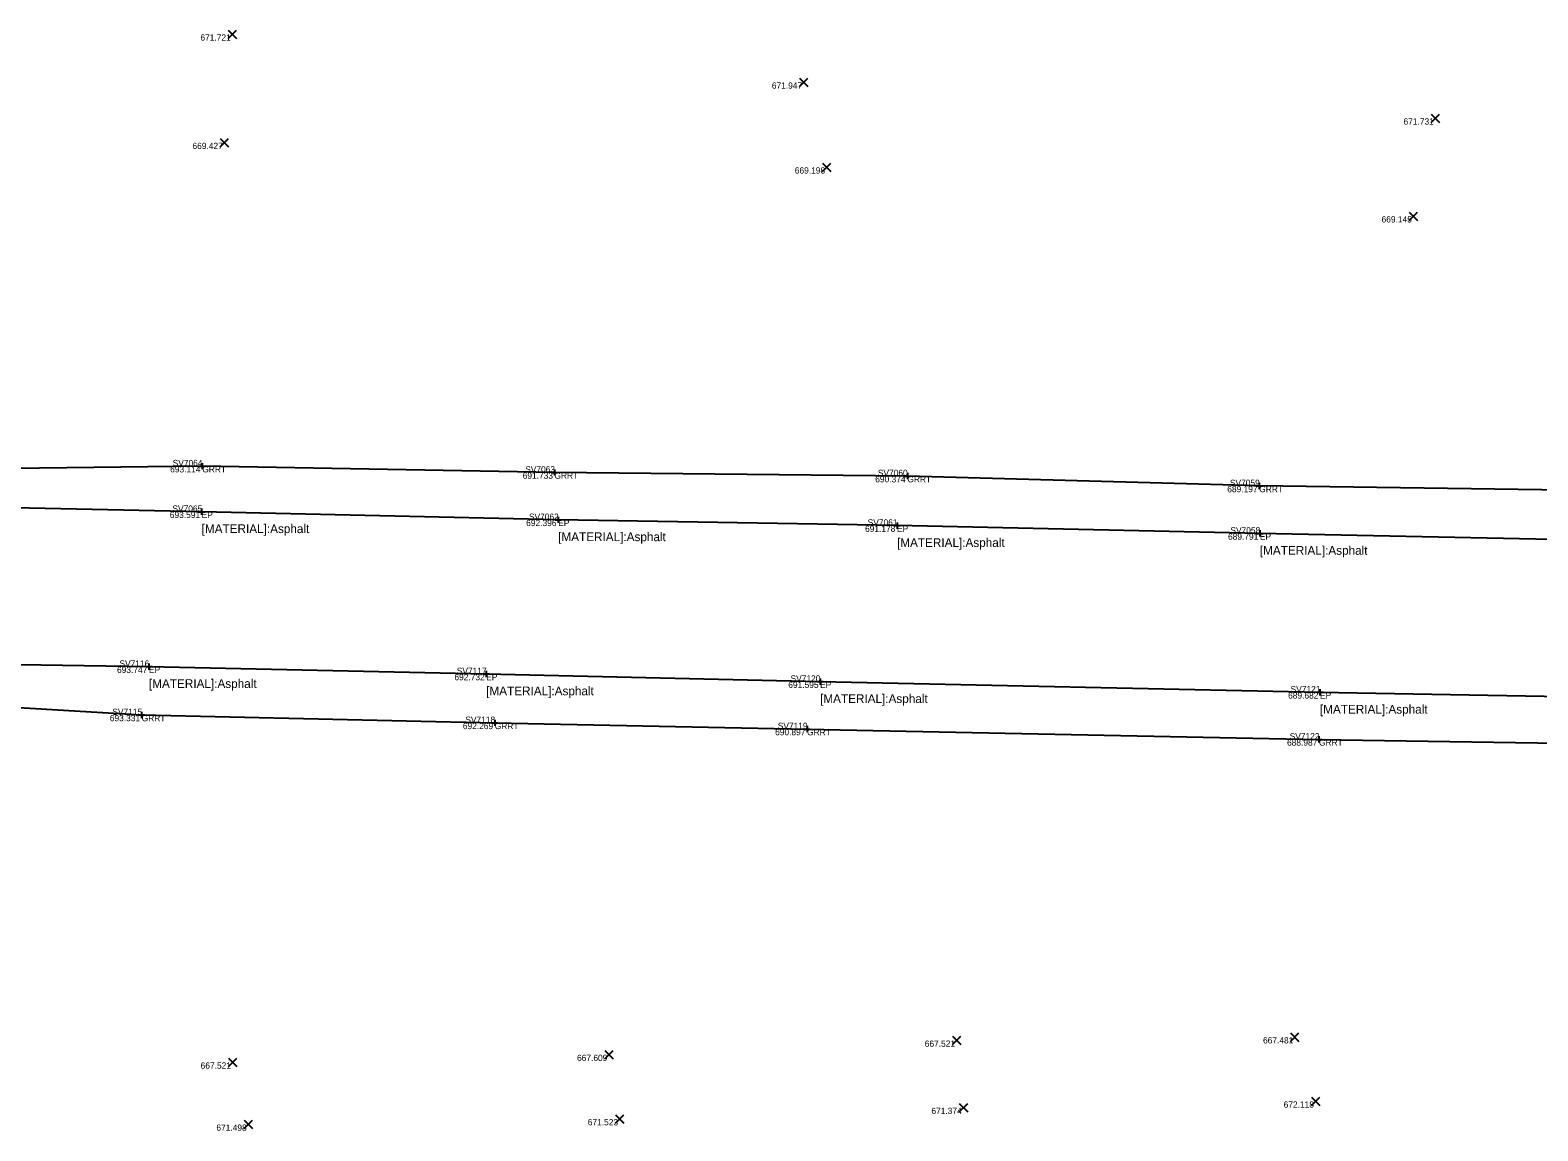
# Model space of a CAD drawing. Extents: x 1660019 to 1662995, y 619975 to 620342.
# Drawn here: x 1661635 to 1661875.4, y 620139.4 to 620314.9 of the extents above; entities that cross this region are included whole.
import ezdxf

# ---------------------------------------------------------------- set-up
doc = ezdxf.new("R2010")
doc.units = 0
for name, color, linetype in [('BR_X_Rail_Object', 7, 'Continuous'), ('PV_X_EOP', 7, 'Continuous'), ('RD_P_GR_Lt', 7, 'Continuous'), ('RD_P_GR_Rt', 7, 'Continuous'), ('RD_X_GR_Bar', 7, 'Continuous'), ('RD_X_GR_Rt', 7, 'Continuous'), ('RD_X_Wall', 7, 'Continuous'), ('SV_X_Text', 7, 'Continuous')]:
    doc.layers.add(name, color=color, linetype=linetype)

msp = doc.modelspace()

# ---------------------------------------------------------------- linework, layer by layer
at = {"layer": 'PV_X_EOP'}
for points in [[(1662111.67, 620229.32), (1662054.93, 620230.37), (1661998.42, 620231.32), (1661945.73, 620232.16), (1661885.47, 620233.5), (1661831.11, 620234.65), (1661773.24, 620235.9), (1661719.2, 620236.82), (1661662.34, 620238.11), (1661602.46, 620239.35), (1661551.29, 620241.52)], [(1661543.6, 620215.08), (1661595.45, 620214.35), (1661653.94, 620213.41), (1661707.72, 620212.24), (1661760.97, 620211.02), (1661840.69, 620209.32), (1661897.28, 620208.31), (1661955.8, 620207.5), (1662009.84, 620206.22), (1662063.33, 620205.17), (1662115.71, 620204.21)]]:
    msp.add_lwpolyline(points, dxfattribs=at)
at = {"layer": 'RD_P_GR_Lt'}
for p, q in [((1661661.94, 620245.38), (1661662.94, 620245.38)), ((1661662.44, 620245.88), (1661662.44, 620244.88)), ((1661662.44, 620245.38), (1661662.44, 620245.38)), ((1661718.1, 620244.37), (1661719.1, 620244.37)), ((1661718.6, 620244.87), (1661718.6, 620243.87)), ((1661718.6, 620244.37), (1661718.6, 620244.37)), ((1661774.39, 620243.8), (1661775.39, 620243.8)), ((1661774.89, 620244.3), (1661774.89, 620243.3)), ((1661774.89, 620243.8), (1661774.89, 620243.8)), ((1661830.51, 620242.22), (1661831.51, 620242.22)), ((1661831.01, 620242.72), (1661831.01, 620241.72)), ((1661831.01, 620242.22), (1661831.01, 620242.22)), ((1661662.34, 620238.61), (1661662.34, 620237.61)), ((1661661.84, 620238.11), (1661662.84, 620238.11)), ((1661662.34, 620238.11), (1661662.34, 620238.11)), ((1661718.7, 620236.82), (1661719.7, 620236.82)), ((1661719.2, 620237.32), (1661719.2, 620236.32)), ((1661719.2, 620236.82), (1661719.2, 620236.82)), ((1661772.74, 620235.9), (1661773.74, 620235.9)), ((1661773.24, 620236.4), (1661773.24, 620235.4)), ((1661773.24, 620235.9), (1661773.24, 620235.9)), ((1661830.61, 620234.65), (1661831.61, 620234.65)), ((1661831.11, 620235.15), (1661831.11, 620234.15)), ((1661831.11, 620234.65), (1661831.11, 620234.65)), ((1661653.44, 620213.41), (1661654.44, 620213.41)), ((1661653.94, 620213.91), (1661653.94, 620212.91)), ((1661653.94, 620213.41), (1661653.94, 620213.41)), ((1661707.22, 620212.24), (1661708.22, 620212.24)), ((1661707.72, 620212.74), (1661707.72, 620211.74)), ((1661707.72, 620212.24), (1661707.72, 620212.24)), ((1661760.47, 620211.02), (1661761.47, 620211.02)), ((1661760.97, 620211.52), (1661760.97, 620210.52)), ((1661760.97, 620211.02), (1661760.97, 620211.02)), ((1661840.19, 620209.32), (1661841.19, 620209.32)), ((1661840.69, 620209.82), (1661840.69, 620208.82)), ((1661840.69, 620209.32), (1661840.69, 620209.32)), ((1661652.27, 620205.71), (1661653.27, 620205.71)), ((1661652.77, 620206.21), (1661652.77, 620205.21)), ((1661652.77, 620205.71), (1661652.77, 620205.71)), ((1661709.09, 620204.95), (1661709.09, 620203.95)), ((1661708.59, 620204.45), (1661709.59, 620204.45)), ((1661709.09, 620204.45), (1661709.09, 620204.45)), ((1661758.4, 620203.47), (1661759.4, 620203.47)), ((1661758.9, 620203.97), (1661758.9, 620202.97)), ((1661758.9, 620203.47), (1661758.9, 620203.47)), ((1661840.54, 620202.31), (1661840.54, 620201.31)), ((1661840.04, 620201.81), (1661841.04, 620201.81)), ((1661840.54, 620201.81), (1661840.54, 620201.81))]:
    msp.add_line(p, q, dxfattribs=at)
at = {"layer": 'RD_P_GR_Rt'}
for p, q in [((1661666.55, 620313.56), (1661667.89, 620314.9)), ((1661666.55, 620314.9), (1661667.89, 620313.56)), ((1661757.71, 620305.89), (1661759.04, 620307.23)), ((1661757.71, 620307.23), (1661759.04, 620305.89)), ((1661858.43, 620300.17), (1661859.77, 620301.51)), ((1661858.43, 620301.51), (1661859.77, 620300.17)), ((1661665.31, 620296.28), (1661666.64, 620297.61)), ((1661665.31, 620297.61), (1661666.64, 620296.28)), ((1661761.38, 620292.36), (1661762.71, 620293.7)), ((1661761.38, 620293.7), (1661762.71, 620292.36)), ((1661854.92, 620284.57), (1661856.26, 620285.9)), ((1661854.92, 620285.9), (1661856.26, 620284.57)), ((1661782.08, 620153.14), (1661783.41, 620154.47)), ((1661782.08, 620154.47), (1661783.41, 620153.14)), ((1661836.02, 620153.66), (1661837.35, 620155)), ((1661836.02, 620155), (1661837.35, 620153.66)), ((1661726.62, 620150.86), (1661727.96, 620152.19)), ((1661726.62, 620152.19), (1661727.96, 620150.86)), ((1661666.6, 620149.64), (1661667.93, 620150.98)), ((1661666.6, 620150.98), (1661667.93, 620149.64)), ((1661839.33, 620143.43), (1661840.67, 620144.76)), ((1661839.33, 620144.76), (1661840.67, 620143.43)), ((1661783.17, 620142.41), (1661784.51, 620143.74)), ((1661783.17, 620143.74), (1661784.51, 620142.41)), ((1661669.13, 620139.75), (1661670.46, 620141.08)), ((1661669.13, 620141.08), (1661670.46, 620139.75)), ((1661728.32, 620140.6), (1661729.65, 620141.93)), ((1661728.32, 620141.93), (1661729.65, 620140.6))]:
    msp.add_line(p, q, dxfattribs=at)
at = {"layer": 'RD_X_GR_Rt'}
for points in [[(1662112.15, 620237.06), (1662055.66, 620238.25), (1661999.68, 620239.27), (1661943.73, 620240.2), (1661887.33, 620241.47), (1661831.01, 620242.22), (1661774.89, 620243.8), (1661718.6, 620244.37), (1661662.44, 620245.38), (1661601.89, 620244.64), (1661537.84, 620244.62)], [(1661527.71, 620211.76), (1661596.63, 620209.07), (1661652.77, 620205.71), (1661709.09, 620204.45), (1661758.9, 620203.47), (1661840.54, 620201.81), (1661896.27, 620200.97), (1661955.33, 620199.48), (1662008.56, 620198.59), (1662063.03, 620197.38), (1662114.92, 620196.42)]]:
    msp.add_lwpolyline(points, dxfattribs=at)

# ---------------------------------------------------------------- texts
at = {"layer": 'BR_X_Rail_Object'}
for s, p in [('GRRT', (1661662.44, 620244.38)), ('GRRT', (1661718.6, 620243.37)), ('GRRT', (1661774.89, 620242.8)), ('GRRT', (1661831.01, 620241.22)), ('EP', (1661662.34, 620237.11)), ('EP', (1661719.2, 620235.82)), ('EP', (1661773.24, 620234.9)), ('EP', (1661831.11, 620233.65)), ('EP', (1661653.94, 620212.41)), ('EP', (1661707.72, 620211.24)), ('EP', (1661760.97, 620210.02)), ('EP', (1661840.69, 620208.32)), ('GRRT', (1661652.77, 620204.71)), ('GRRT', (1661709.09, 620203.45)), ('GRRT', (1661758.9, 620202.47)), ('GRRT', (1661840.54, 620200.81))]:
    msp.add_text(s, height=1, dxfattribs=at).set_placement(p)
at = {"layer": 'RD_X_GR_Bar'}
for s, p in [('671.721', (1661662.14, 620313.23)), ('671.947', (1661753.28, 620305.56)), ('671.731', (1661854.02, 620299.84)), ('669.427', (1661660.88, 620295.94)), ('669.198', (1661756.94, 620292.03)), ('669.145', (1661850.52, 620284.23)), ('693.114', (1661657.32, 620244.38)), ('691.733', (1661713.54, 620243.37)), ('690.374', (1661769.77, 620242.8)), ('689.197', (1661825.91, 620241.22)), ('693.591', (1661657.26, 620237.11)), ('692.396', (1661714.1, 620235.82)), ('691.178', (1661768.14, 620234.9)), ('689.791', (1661826.03, 620233.65)), ('693.747', (1661648.84, 620212.41)), ('692.732', (1661702.65, 620211.24)), ('691.595', (1661755.9, 620210.02)), ('689.682', (1661835.61, 620208.32)), ('693.331', (1661647.69, 620204.71)), ('692.269', (1661704, 620203.45)), ('690.897', (1661753.8, 620202.47)), ('688.987', (1661835.44, 620200.81)), ('667.481', (1661831.61, 620153.33)), ('667.521', (1661777.66, 620152.8)), ('667.521', (1661662.18, 620149.31)), ('667.609', (1661722.21, 620150.53)), ('671.374', (1661778.72, 620142.08)), ('672.118', (1661834.9, 620143.09)), ('671.498', (1661664.69, 620139.41)), ('671.523', (1661723.92, 620140.27))]:
    msp.add_text(s, height=1, dxfattribs=at).set_placement(p)
at = {"layer": 'RD_X_Wall'}
for s, p in [('SV7064', (1661657.72, 620245.38)), ('SV7063', (1661713.94, 620244.37)), ('SV7060', (1661770.18, 620243.8)), ('SV7059', (1661826.33, 620242.22)), ('SV7065', (1661657.68, 620238.11)), ('SV7062', (1661714.53, 620236.82)), ('SV7061', (1661768.56, 620235.9)), ('SV7058', (1661826.41, 620234.65)), ('SV7116', (1661649.23, 620213.41)), ('SV7117', (1661703.03, 620212.24)), ('SV7120', (1661756.26, 620211.02)), ('SV7121', (1661836.01, 620209.32)), ('SV7115', (1661648.1, 620205.71)), ('SV7118', (1661704.39, 620204.45)), ('SV7119', (1661754.22, 620203.47)), ('SV7122', (1661835.86, 620201.81))]:
    msp.add_text(s, height=1, dxfattribs=at).set_placement(p)
at = {"layer": 'SV_X_Text'}
for p in [(1661662.34, 620234.71), (1661719.2, 620233.42), (1661773.24, 620232.49), (1661831.11, 620231.25), (1661653.94, 620210.01), (1661707.72, 620208.84), (1661760.97, 620207.61), (1661840.69, 620205.92)]:
    msp.add_text('[MATERIAL]:Asphalt', height=1.4, dxfattribs=at).set_placement(p)

doc.saveas('drawing.dxf')
